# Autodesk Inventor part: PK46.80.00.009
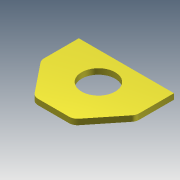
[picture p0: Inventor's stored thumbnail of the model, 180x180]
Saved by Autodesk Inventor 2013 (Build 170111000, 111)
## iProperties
Shininess: 64.0
Length Units: 11269
Angle Units: 11279
Time Units: 11290
Mass Units: 11283
Length Display Precision: 3
Angle Display Precision: 2
Compacted: True
Part Number: PK46.80.00.009
Document SubType Name: Modeling
Created: 2005-01
Material: Steel, Mild
Designer: SAlex
Manufacturer: Standard
Standards Organization: Custom
Density: 7.86 g/cm^3
Mass: 10140.6 g
Surface Area: 1578.47 cm^2
Volume: 1290.15 cm^3
Density: 0.0
Volumn: 0.0
Area: 0.0
PropertySet Name: Model Information
Control State: 0
Master: False
Checked Out: False
Checked Out Date: 2008-10-15
Last Check In Date: 2008-10-15
Author: SAlex
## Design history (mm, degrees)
sketch "Sketch1"
  geometry: L1 (0, 0)-(340, 0); L2 (340, 0)-(340, -135); L3 (340, -135)-(240, -260); L4 (240, -260)-(100, -260); L5 (100, -260)-(0, -135); L6 (0, -135)-(0, 0); C1 r 60 at (170, -100)
  constraints: 12 end point, 2 equal length, 2 parallel, 1 centre point, 1 horizontal, 1 perpendicular, 1 other
  dimensions: "d0" = 340 distance of L1.start L1.end; "d1" = 260 distance between parallel lines of L1 L4; "d2" = 100 horizontal distance of L4.end L5.end; "d3" = 120 diameter of C1; "d4" = 170 distance from line of C1.centre L6 (= 0.5 x d0); "d5" = 100 distance from line of L1 C1.centre; "d6" = 135 distance of L5.end L1.start
extrude "Extrusion1" new body sketch "Sketch1" distance "d7" = 20; taper "d8" = 0 deg
fillet "Fillet1" dims "d9" = 30
body "Solid1"
